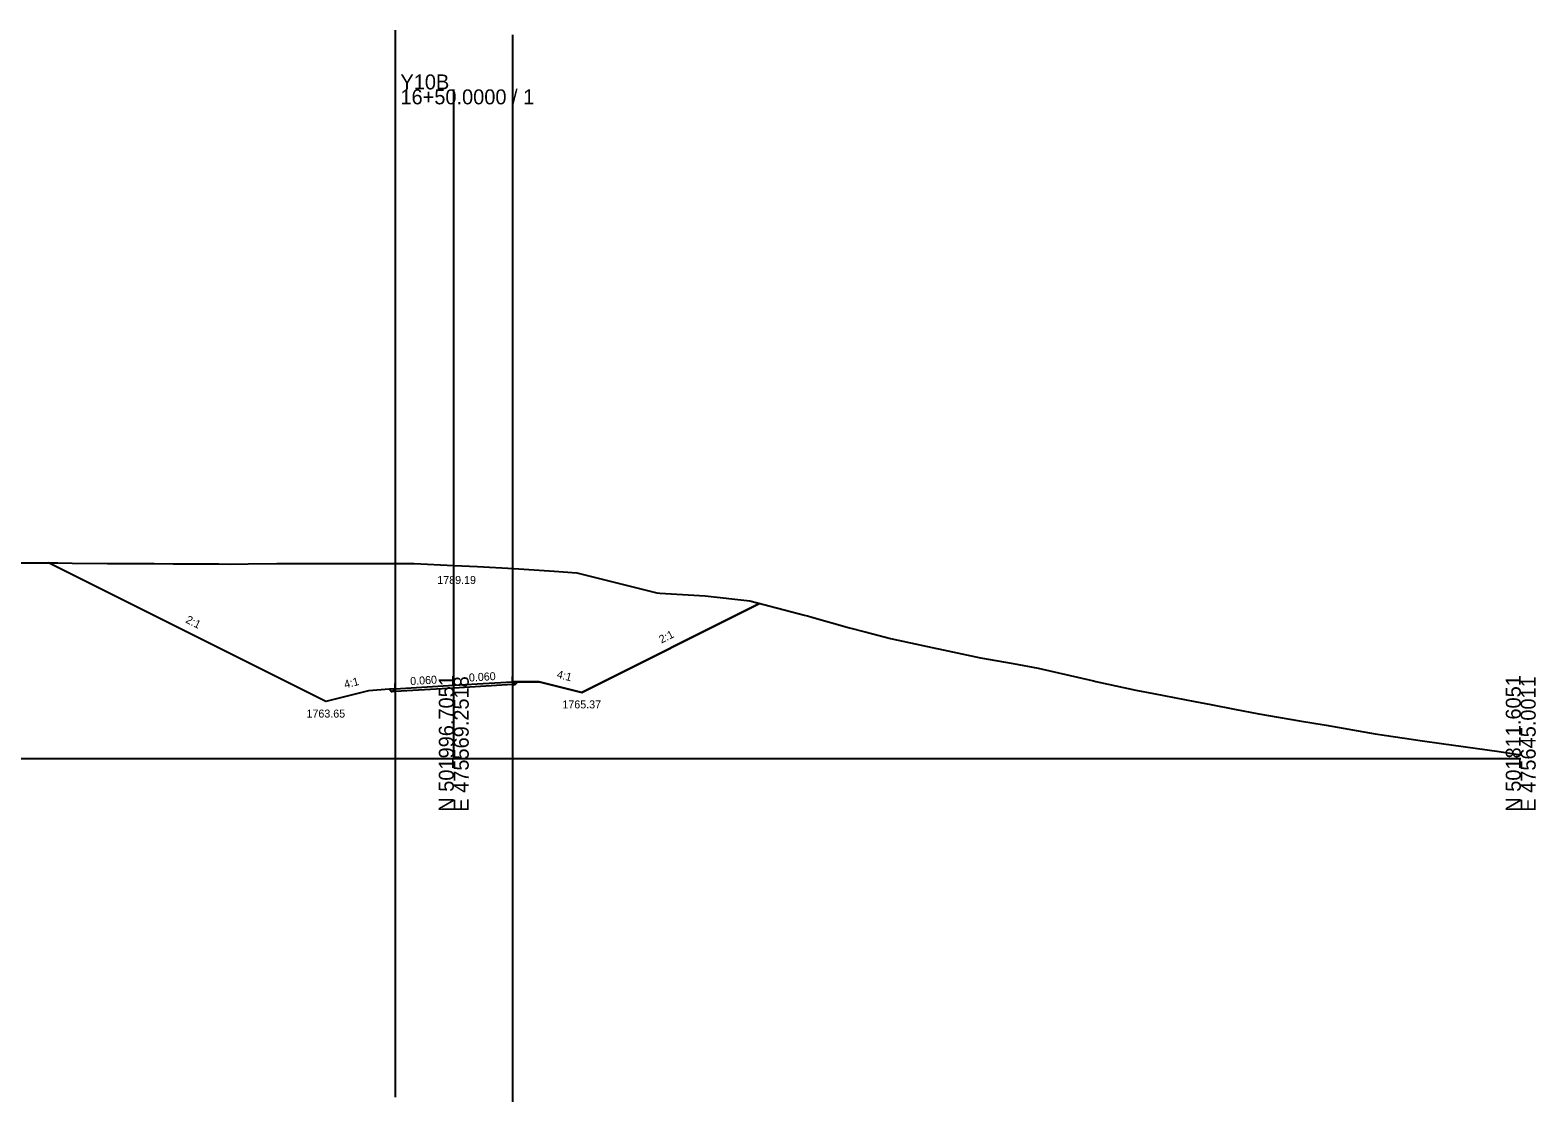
# Model space of a CAD drawing. Extents: x -26 to 1803, y -10 to 9558.
# Drawn here: x 120.6 to 402.8, y 6435.6 to 6636.5 of the extents above; entities that cross this region are included whole.
import ezdxf

# ---------------------------------------------------------------- set-up
doc = ezdxf.new("R2010")
doc.units = 0
for name, color, linetype in [('Exist Cross Section Cell', 7, 'Continuous'), ('Exist XS Center Line Elevation Label', 7, 'Continuous'), ('Exist XS Ground Line', 7, 'Continuous'), ('Prop XS Ditch Slope Text', 7, 'Continuous'), ('Prop XS Ditch Standard Text', 7, 'Continuous'), ('Prop XS Dump Level', 7, 'Continuous'), ('Prop XS Earthwork Shape', 7, 'Continuous'), ('Prop XS EOT Tick Mark', 7, 'Continuous'), ('Prop XS Finish Grade', 7, 'Continuous'), ('Prop XS Finish Grade Earthwork', 7, 'Continuous'), ('Prop XS Finish Grade Pavement', 7, 'Continuous'), ('Prop XS Hydro Typical Ditch Data', 7, 'Continuous'), ('Prop XS Pvmt Edge Slope', 7, 'Continuous'), ('Prop XS SE Text', 7, 'Continuous'), ('Prop XS Shoulder Borrow Shape', 7, 'Continuous'), ('Prop XS Side Slope Text', 7, 'Continuous'), ('Prop XS Subgrade Earthwork', 7, 'Continuous'), ('Scratch_Level_2', 7, 'Continuous')]:
    doc.layers.add(name, color=color, linetype=linetype)

msp = doc.modelspace()

# ---------------------------------------------------------------- linework, layer by layer
at = {"layer": 'Exist Cross Section Cell'}
for p, q in [((200, 6500), (200, 6625.41)), ((0, 6500), (200, 6500)), ((200, 6500), (400, 6500))]:
    msp.add_line(p, q, dxfattribs=at)
at = {"layer": 'Exist XS Ground Line'}
msp.add_lwpolyline([(115, 6536.69), (120.82, 6536.66), (125.8, 6536.63), (128.49, 6536.58), (135.07, 6536.54), (136.16, 6536.53), (136.61, 6536.53), (143.83, 6536.54), (147.42, 6536.48), (155.97, 6536.47), (158.22, 6536.44), (161.47, 6536.47), (166.84, 6536.54), (169.03, 6536.53), (174.51, 6536.52), (179.84, 6536.51), (187.88, 6536.52), (190.65, 6536.52), (192.56, 6536.52), (200, 6536.19), (204.43, 6536), (211.24, 6535.6), (218.8, 6535.11), (223.09, 6534.81), (236.32, 6531.48), (238.08, 6531.02), (238.65, 6530.99), (247.15, 6530.45), (255.49, 6529.51), (265.73, 6526.84), (266.29, 6526.72), (267.11, 6526.49), (274.2, 6524.48), (277.1, 6523.71), (281.87, 6522.5), (287.91, 6521.19), (293.51, 6519.96), (298.72, 6518.85), (304.87, 6517.77), (309.52, 6516.9), (312.54, 6516.21), (319.92, 6514.51), (320.33, 6514.42), (327.88, 6512.78), (331.14, 6512.14), (338.91, 6510.67), (341.94, 6510.09), (346.33, 6509.24), (350.89, 6508.37), (352.75, 6508.03), (358.55, 6507.05), (363.56, 6506.22), (372.74, 6504.61), (374.37, 6504.34), (381.56, 6503.29), (385.17, 6502.78), (389.23, 6502.22), (395.98, 6501.27), (399.15, 6500.81), (400, 6500.69)], dxfattribs=at)
at = {"layer": 'Prop XS Dump Level'}
for p, q in [((200, 6513.71), (211, 6514.37)), ((189, 6513.05), (200, 6513.71))]:
    msp.add_line(p, q, dxfattribs=at)
at = {"layer": 'Prop XS Earthwork Shape'}
msp.add_lwpolyline([(184, 6512.65), (176, 6510.65), (124.02, 6536.64), (125.8, 6536.63), (128.49, 6536.58), (135.07, 6536.54), (136.16, 6536.53), (136.61, 6536.53), (143.83, 6536.54), (147.42, 6536.48), (155.97, 6536.47), (158.22, 6536.44), (161.47, 6536.47), (166.84, 6536.54), (169.03, 6536.53), (174.51, 6536.52), (179.84, 6536.51), (187.88, 6536.52), (190.65, 6536.52), (192.56, 6536.52), (200, 6536.19), (204.43, 6536), (211.24, 6535.6), (218.8, 6535.11), (223.09, 6534.81), (236.32, 6531.48), (238.08, 6531.02), (238.65, 6530.99), (247.15, 6530.45), (255.49, 6529.51), (257.32, 6529.03), (224, 6512.37), (216, 6514.37), (212.02, 6514.37), (211.51, 6513.86), (211, 6513.83), (200, 6513.17), (189, 6512.51), (188.42, 6512.48), (187.93, 6512.97)], close=True, dxfattribs=at)
at = {"layer": 'Prop XS EOT Tick Mark'}
for p, q in [((211, 6514.37), (211, 6515.37)), ((189, 6513.05), (189, 6514.05))]:
    msp.add_line(p, q, dxfattribs=at)
at = {"layer": 'Prop XS Finish Grade'}
for p, q in [((211, 6514.37), (212.02, 6514.37)), ((189, 6513.05), (187.93, 6512.97))]:
    msp.add_line(p, q, dxfattribs=at)
at = {"layer": 'Prop XS Finish Grade Earthwork'}
for p, q in [((176, 6510.65), (124.02, 6536.64)), ((224, 6512.37), (257.32, 6529.03)), ((212.02, 6514.37), (216, 6514.37)), ((216, 6514.37), (224, 6512.37)), ((184, 6512.65), (176, 6510.65)), ((187.93, 6512.97), (184, 6512.65))]:
    msp.add_line(p, q, dxfattribs=at)
at = {"layer": 'Prop XS Finish Grade Pavement'}
for p, q in [((200, 6513.71), (211, 6514.37)), ((189, 6513.05), (200, 6513.71))]:
    msp.add_line(p, q, dxfattribs=at)
at = {"layer": 'Prop XS Hydro Typical Ditch Data'}
for p, q in [((176, 6510.65), (124.02, 6536.64)), ((224, 6512.37), (257.32, 6529.03)), ((216, 6514.37), (224, 6512.37)), ((184, 6512.65), (176, 6510.65))]:
    msp.add_line(p, q, dxfattribs=at)
at = {"layer": 'Prop XS Pvmt Edge Slope'}
for p, q in [((211, 6514.37), (211.51, 6513.86)), ((189, 6513.05), (188.42, 6512.48))]:
    msp.add_line(p, q, dxfattribs=at)
at = {"layer": 'Prop XS Shoulder Borrow Shape'}
for points in [[(211, 6514.37), (211.51, 6513.86), (212.02, 6514.37)], [(189, 6513.05), (187.93, 6512.97), (188.42, 6512.48)]]:
    msp.add_lwpolyline(points, close=True, dxfattribs=at)
at = {"layer": 'Prop XS Subgrade Earthwork'}
for p, q in [((211.51, 6513.86), (212.02, 6514.37)), ((188.42, 6512.48), (187.93, 6512.97)), ((189, 6512.51), (188.42, 6512.48)), ((200, 6513.17), (189, 6512.51)), ((211, 6513.83), (200, 6513.17)), ((211, 6513.83), (211.51, 6513.86))]:
    msp.add_line(p, q, dxfattribs=at)
at = {"layer": 'Scratch_Level_2'}
for p, q in [((189, 6636.52), (189, 6436.52)), ((211, 6635.61), (211, 6435.61))]:
    msp.add_line(p, q, dxfattribs=at)

# ---------------------------------------------------------------- texts
at = {"layer": 'Exist Cross Section Cell'}
for s, p in [('Y10B', (190, 6625.41)), ('16+50.0000 / 1', (190, 6622.61))]:
    msp.add_text(s, height=2.8, dxfattribs=at).set_placement(p)
for s, p in [('N 501996.7051', (200, 6490)), ('E 475569.2518', (202.8, 6490)), ('N 501811.6051', (400, 6490)), ('E 475645.0011', (402.8, 6490))]:
    msp.add_text(s, height=2.8, rotation=90, dxfattribs=at).set_placement(p)
at = {"layer": 'Exist XS Center Line Elevation Label'}
msp.add_text('1789.19', height=1.5, dxfattribs=at).set_placement((196.91, 6532.69))
at = {"layer": 'Prop XS Ditch Slope Text'}
for rotation, p in [(14.0362, (179.64, 6513.11)), (345.9638, (219.21, 6515.12))]:
    msp.add_text('4:1', height=1.5, rotation=rotation, dxfattribs=at).set_placement(p)
at = {"layer": 'Prop XS Ditch Standard Text'}
for s, p in [('1763.65', (172.39, 6507.65)), ('1765.37', (220.36, 6509.37))]:
    msp.add_text(s, height=1.5, dxfattribs=at).set_placement(p)
at = {"layer": 'Prop XS Dump Level'}
for p in [(216, 6514.33), (184, 6512.61)]:
    msp.add_text('Case1', height=0.04, dxfattribs=at).set_placement(p)
at = {"layer": 'Prop XS SE Text'}
for p in [(191.88, 6513.73), (202.88, 6514.39)]:
    msp.add_text('0.060', height=1.5, rotation=3.4336, dxfattribs=at).set_placement(p)
at = {"layer": 'Prop XS Side Slope Text'}
for rotation, p in [(333.4349, (149.62, 6525.52)), (26.5651, (238.93, 6521.51))]:
    msp.add_text('2:1', height=1.5, rotation=rotation, dxfattribs=at).set_placement(p)

doc.saveas('drawing.dxf')
